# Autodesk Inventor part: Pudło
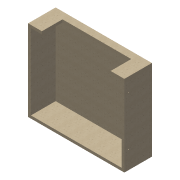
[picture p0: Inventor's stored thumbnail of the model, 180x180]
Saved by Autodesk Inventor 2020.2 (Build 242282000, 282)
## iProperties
Created: 2005-10
Part Number: Pudło
Document SubType Name: Modeling
Designer: F.Stasiak
Density: 1 g/cm^3
Material: Ogólny
Appearance: Drewno (sklejka gat. B)
Manager: www.cadconsulting.pl
Company: Fabian Stasiak CAD Consulting
Author: F.Stasiak
Subject: Zbiór ćwiczeń. Autodesk Inventor 2020. Kurs podstawowy
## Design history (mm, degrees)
sketch "Szkic1"
  geometry: L1 (359.41, -29.175)-(9.41, -29.175); L2 (9.41, -29.175)-(9.41, -129.175); L3 (9.41, -129.175)-(359.41, -129.175); L4 (359.41, -129.175)-(359.41, -29.175)
  constraints: 8 end point, 2 parallel, 1 horizontal, 1 perpendicular
  dimensions: "d0" = 100 distance of L1.end L2.end; "d1" = 350 distance of L2.end L3.end
extrude "Wyciągnięcie proste1" new body sketch "Szkic1" distance "d2" = 295; taper "d3" = 0 deg
feature "Skorupa1" dims "d4" = 10
sketch "Szkic2"
  geometry: L1 (359.41, -29.175)-(9.41, -29.175) reference; L2 (9.41, -29.175)-(9.41, -129.175) reference; L3 (9.41, -129.175)-(359.41, -129.175) reference; L4 (359.41, -129.175)-(359.41, -29.175) reference; L5 (309.41, -129.175)-(59.41, -129.175); L6 (59.41, -129.175)-(59.41, -54.175); L7 (59.41, -54.175)-(309.41, -54.175); L8 (309.41, -54.175)-(309.41, -129.175); L9 (9.41, -129.175)-(359.41, -129.175) reference
  constraints: 8 end point, 2 parallel, 1 collinear, 1 horizontal, 1 perpendicular
  dimensions: "d5" = 50 distance between parallel lines of L8 L4; "d6" = 50 distance between parallel lines of L2 L6; "d7" = 25 distance between parallel lines of L1 L7
extrude "Wyciągnięcie proste2" cut sketch "Szkic2" stored distance "d8" = 295; taper "d9" = 0 deg
node "Płaszczyzna konstrukcyjna1"
sketch "Szkic3"
  geometry: L1 (14.679, 21)-(274.679, 21) reference; C1 r 1.5 at (49.679, 15) reference; C2 r 1.5 at (229.679, 15) reference
hole "Otwór1" sketch "Szkic3" at (49.679, 15), (229.679, 15) diameter "d10" = 3; stored, may be unused: countersink angle "d14" = 90 deg, drill point angle "d16" = 118 deg; dims "d11" = 6, "d12" = 4, "d13" = 2, "d15" = 8
sketch "Szkic4"
  geometry: C1 r 3 at (-49.928, 15) reference; C2 r 3 at (-229.928, 15) reference
hole "Otwór2" sketch "Szkic4" at (-49.928, 15), (-229.928, 15) diameter "d17" = 3; stored, may be unused: countersink angle "d21" = 90 deg, drill point angle "d23" = 118 deg; dims "d18" = 6, "d19" = 4, "d20" = 2, "d22" = 8
node "Bryła1"
node "Korpusy bryłowe"
node "Korpusy powierzchniowe"
node "Pętla rzutowana1"
node "Odniesienie1"
node "Odniesienie2"
node "Odniesienie3"
node "Odniesienie4"
node "Odniesienie5"
